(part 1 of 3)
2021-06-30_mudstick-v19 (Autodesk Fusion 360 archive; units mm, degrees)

design "Mudstick" references "Mudstick Plate", "2298K420_METRIC QUICK-GRIP SCREW-CLAMP BUSHING", "N17 48mm"
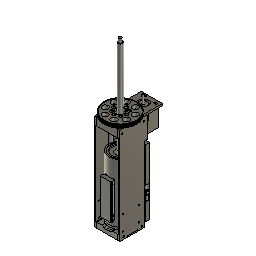
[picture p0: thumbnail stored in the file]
parameter "flexure_w" = 1.5
parameter "gap_w" = 1
parameter "t_sheet_main" = 6.6
parameter "tube_wallthick" = 3.3
parameter "tube_id" = 50.8 (= "( 25.4 * 2 ) * 1 mm")
parameter "tube_len" = 149.225 (= "( 6 * 25.4 ) * 1 mm - ( 0.125 * 25.4 ) * 1 mm")
parameter "id_bspushbearing" = 40
parameter "od_bspushbearing" = 52
parameter "t_bspushbearing" = 7
parameter "hw_m4insert_d" = 5.8
parameter "hw_m4insert_l" = 4.6
parameter "p_teeth" = 2
parameter "pd_pinion" = 10.1859 (= "p_teeth * nt_pinion / PI")
parameter "pd_driven" = 81.4873 (= "p_teeth * nt_driven / PI")
parameter "belt_length" = 280
parameter "c_dist_manuel" = 56.6
parameter "d101" = 7 (= "t_bspushbearing")
parameter "d118" = 2.15 (= "( 4.3 / 2 ) * 1 mm")
sketch "Sketch1" plane through (0, 0, 0) normal (0, 1, 0) x axis (1, 0, 0)
  line L1 (70, 0) -> (0, 0)
  line L2 (70, -115) -> (70, 0)
  line L3 (0, -115) -> (70, -115)
  line L4 (0, 0) -> (0, -115)
  line L5 (35, 0) -> (35, -115)
  point P1 (0, 0)
  point P2 (0, 0)
  point P6 (35, -115)
  point P7 (35, 0)
  point P4 (70, -115)
  point P5 (0, -115)
  horizontal L1
  vertical L2
  horizontal L3
  coincident P1 P2
  vertical L4
  midpoint L3 P6
  midpoint L1 P7
  dimension "d1" distance P4 P5 = 70
  dimension "d2" distance P2 P5 = 115
extrude "Extrude3" new body sketch "Sketch1" profile of L1 L3 L4 L5 against normal blind 10 bodies "Home Plate"
mirror "Mirror3" mirrorStitchTolerance 0
combine "Combine2"
work_plane "WorkPlane1"
sketch "Revolve" plane through (35, -3.3, 55) normal (-1, 0, 0) x axis (0, 1, 0)
  line L1 (-11.3, 46.5347) -> (-8, 46.5347)
  line L2 (-11.3, -102.6903) -> (-11.3, 46.5347)
  line L3 (-36.7, 46.5347) -> (-11.3, 46.5347)
  line L4 (-36.7, -445) -> (-36.7, 155)
  line L5 (-8, -102.6903) -> (-8, 46.5347)
  line L6 (-11.3, -102.6903) -> (-8, -102.6903)
  line L7 (-11.35, 46.5847) -> (-8, 46.5847)
  line L8 (-11.35, 40.5847) -> (-11.35, 46.5847)
  line L9 (-13.35, 40.5847) -> (-11.35, 40.5847)
  line L10 (-34.7, 52.9112) -> (-13.35, 40.5847)
  line L11 (-34.7, 67) -> (-34.7, 52.9112)
  line L12 (-8, 46.5847) -> (-8, 51.5847)
  line L13 (-8, 51.5847) -> (-34.7, 67)
  line L14 (-36.7, -42.863) -> (-11.8, -54.4741)
  line L15 (-7.7, -159.2448) -> (-10.7, -159.2448)
  line L16 (-10.7, -164.2448) -> (-10.7, -159.2448)
  line L17 (-13.7, -167.2448) -> (-10.7, -164.2448)
  line L18 (-13.7, -171.2448) -> (-13.7, -167.2448)
  line L19 (-10.7, -174.2448) -> (-13.7, -171.2448)
  line L20 (-10.7, -179.2448) -> (-10.7, -174.2448)
  line L21 (-7.7, -179.2448) -> (-10.7, -179.2448)
  line L22 (-7.7, -159.2448) -> (-7.7, -179.2448)
  line L23 (-16.7, -177.9448) -> (-15.4, -179.2448)
  line L24 (-16.7, -163.2448) -> (-16.7, -177.9448)
  line L25 (-25.45, -163.2448) -> (-16.7, -163.2448)
  line L26 (-25.45, -189.7448) -> (-25.45, -163.2448)
  line L27 (-16.7, -160.5448) -> (-16.7, -162.7448)
  line L28 (-15.4, -159.2448) -> (-16.7, -160.5448)
  line L29 (-14.7, -159.2448) -> (-15.4, -159.2448)
  line L30 (-14.7, -156.2448) -> (-14.7, -159.2448)
  line L31 (-25.45, -156.2448) -> (-14.7, -156.2448)
  line L32 (-25.45, -162.7448) -> (-25.45, -156.2448)
  line L33 (-16.7, -162.7448) -> (-25.45, -162.7448)
  line L34 (-14.7, -179.2448) -> (-15.4, -179.2448)
  line L35 (-14.7, -180.7448) -> (-14.7, -179.2448)
  line L36 (4.0437, -189.7448) -> (-25.45, -189.7448)
  line L37 (4.0437, -180.7448) -> (-14.7, -180.7448)
  line L38 (4.0437, -189.7448) -> (4.0437, -180.7448)
  line L39 (-16.7, -166.2448) -> (-12.7, -166.2448)
  line L40 (14.807, -180.7448) -> (14.807, -189.7448)
  line L41 (19.9, -180.7448) -> (14.807, -180.7448)
  line L42 (19.9, -189.7448) -> (19.9, -180.7448)
  line L43 (14.807, -189.7448) -> (19.9, -189.7448)
  line L44 (41.05, -127.2448) -> (-1.25, -127.2448)
  line L45 (41.05, -175.2448) -> (41.05, -127.2448)
  line L46 (-1.25, -175.2448) -> (41.05, -175.2448)
  line L47 (-1.25, -127.2448) -> (-1.25, -175.2448)
  line L48 (41.05, -175.2448) -> (-1.25, -127.2448)
  line L49 (-1.25, -175.2448) -> (41.05, -127.2448)
  line L50 (-32.7, -51.2448) -> (-36.7, -51.2448)
  line L51 (-32.7, -66.2448) -> (-32.7, -51.2448)
  line L52 (-31.7, -66.2448) -> (-32.7, -66.2448)
  line L53 (-30.7, -341.2448) -> (-30.7, -104.2448)
  line L54 (-32.7, -341.2448) -> (-30.7, -341.2448)
  line L55 (-32.7, -351.2448) -> (-32.7, -341.2448)
  line L56 (-36.7, -351.2448) -> (-32.7, -351.2448)
  line L57 (-36.7, -53.8968) -> (-19.0837, -62.1114)
  line L58 (-15.5773, -102.1903) -> (-11.8, -102.1903)
  line L59 (-11.8, -58.1903) -> (-11.9581, -58.1903)
  line L60 (-11.8, -54.4741) -> (-11.8, -55.4741)
  line L61 (-12.3, -60.6903) -> (-11.8, -60.1903)
  line L62 (-12.3, -95.9741) -> (-12.3, -60.6903)
  line L63 (-11.9581, -100.1903) -> (-11.8, -100.1903)
  line L64 (-11.8, -96.4741) -> (-11.8, -97.4741)
  line L65 (-12.3, -95.9741) -> (-11.8, -96.4741)
  line L66 (-11.8, -55.4741) -> (-11.9581, -55.4741)
  line L67 (-11.8, -97.4741) -> (-11.9581, -97.4741)
  line L68 (-11.8, -97.4741) -> (-11.8, -58.1903)
  line L69 (-11.8, -102.1903) -> (-11.8, -97.4741)
  line L70 (-16.7, -148.2448) -> (-16.7, -156.2448)
  line L71 (-30.7, -148.2448) -> (-16.7, -148.2448)
  line L72 (-15.5773, -102.1903) -> (-19.0837, -62.1114)
  line L73 (-9, 49.0847) -> (-8, 47.0847)
  line L74 (-8, 51.0847) -> (-9, 49.0847)
  line L75 (-8, 49.0847) -> (-9, 49.0847)
  line L76 (-31.7, -104.2448) -> (-31.7, -66.2448)
  line L77 (-30.7, -104.2448) -> (-31.7, -104.2448)
  line L78 (-25.2, -104.1448) -> (-31.7, -104.1448)
  line L79 (-25.2, -78.1448) -> (-25.2, -104.1448)
  line L80 (-31.7, -78.1448) -> (-25.2, -78.1448)
  line L81 (-31.7, -104.1448) -> (-31.7, -78.1448)
  line L82 (-31.7, -51.1594) -> (-31.7, -56.2283)
  line L83 (-36.7, -48.8279) -> (-31.7, -51.1594)
  line L84 (-25.1, -78.0448) -> (-28.7, -78.0448)
  line L85 (-25.1, -99.1448) -> (-25.1, -78.0448)
  line L86 (-19.3454, -61.9894) -> (-16.0947, -99.1448)
  line L87 (-28.7, -77.0448) -> (-28.7, -78.0448)
  line L88 (-30.7, -74.6613) -> (-28.7, -77.0448)
  line L89 (-30.7, -56.6946) -> (-30.7, -74.6613)
  line L90 (-18.178, -72.4641) -> (-30.7, -66.625)
  line L91 (-15.8414, -99.1719) -> (-11.9581, -98.8322)
  line L92 (-16.0947, -99.1448) -> (-25.1, -99.1448)
  line L93 (4.3937, -189.392) -> (4.3937, -189.7448)
  line L94 (2.8397, -188.4948) -> (4.3937, -189.392)
  line L95 (2.8397, -189.7448) -> (2.8397, -188.4948)
  line L96 (4.3937, -189.7448) -> (4.0437, -189.7448)
  line L97 (-25.45, -185.2448) -> (4.0437, -185.2448)
  line L98 (2.8397, -181.9948) -> (4.3937, -181.0976)
  line L99 (4.3937, -180.7448) -> (4.0437, -180.7448)
  line L100 (4.3937, -181.0976) -> (4.3937, -180.7448)
  line L101 (2.8397, -180.7448) -> (2.8397, -181.9948)
  line L102 (-11.9581, 43.5847) -> (-11.9581, -56.8322)
  line L103 (-11.9581, 42.2266) -> (-11.35, 42.2266)
  line L104 (-11.35, 44.9428) -> (-11.9581, 44.9428)
  line L105 (-11.9581, 43.5847) -> (-11.35, 43.5847)
  circle C1 centre (-11.9581, -56.8322) radius 1.3081
  arc A1 centre (-11.9581, -56.8322) radius 1.3581 clockwise from (-11.9581, -58.1903) to (-11.9581, -55.4741)
  circle C2 centre (-11.9581, -98.8322) radius 1.3081
  arc A2 centre (-11.9581, -98.8322) radius 1.3581 clockwise from (-11.9581, -100.1903) to (-11.9581, -97.4741)
  circle C3 centre (-11.9581, 43.5847) radius 1.3081
  arc A3 centre (-11.9581, 43.5847) radius 1.3581 clockwise from (-11.9581, 42.2266) to (-11.9581, 44.9428)
  point P4 (-11.3, -102.6903)
  point P10 (-11.3, -102.6903)
  point P5 (-36.7, 46.5347)
  point P11 (-8, 46.5847)
  point P18 (-8, 46.5847)
  point P2 (-8, 46.5347)
  point P16 (-34.7, 67)
  point P19 (-34.7, 67)
  point P21 (-36.7, -42.863)
  point P28 (-10.7, -174.2448)
  point P24 (-7.7, -159.2448)
  point P31 (-7.7, -159.2448)
  point P37 (-16.7, -162.7448)
  point P44 (-16.7, -162.7448)
  point P35 (-25.45, -163.2448)
  point P23 (-10.7, -159.2448)
  point P29 (-10.7, -179.2448)
  point P40 (-14.7, -159.2448)
  point P50 (-12.7, -166.2448)
  point P51 (-16.7, -166.2448)
  point P52 (14.807, -189.7448)
  point P56 (14.807, -189.7448)
  point P61 (19.9, -151.2448)
  point P54 (19.9, -180.7448)
  point P49 (4.0437, -189.7448)
  point P48 (4.0437, -180.7448)
  point P62 (-36.7, -51.2448)
  point P68 (-36.7, -351.2448)
  point P71 (-36.7, -53.8968)
  point P73 (-10.65, -56.8322)
  point P72 (-11.9581, -56.8322)
  point P74 (-11.9581, -56.8322)
  point P20 (-11.8, -54.4741)
  point P77 (-11.8, -54.4741)
  point P78 (-11.8, -60.1903)
  point P81 (-11.9581, -98.8322)
  point P82 (-11.8, -100.1903)
  point P84 (-11.9581, -98.8322)
  point P80 (-12.3, -95.9741)
  point P86 (-12.3, -95.9741)
  point P76 (-11.8, -58.1903)
  point P90 (-11.8, -97.4741)
  point P47 (4.0437, -189.7448)
  point P91 (-16.7, -156.2448)
  point P93 (-30.7, -148.2448)
  point P94 (-8, 47.0847)
  point P96 (-8, 51.0847)
  point P97 (-8, 49.0847)
  point P105 (-31.7, -82.2448)
  point P106 (-31.7, -56.2283)
  point P108 (-36.7, -48.8279)
  point P116 (-30.7, -56.6946)
  point P113 (-19.3454, -61.9894)
  point P117 (-30.7, -66.625)
  point P118 (-18.178, -72.4641)
  point P119 (-11.9581, -98.8322)
  point P120 (-15.8414, -99.1719)
  point P121 (-13.311, -98.9505)
  point P125 (2.8397, -189.7448)
  point P126 (4.0437, -185.2448)
  point P127 (-25.45, -185.2448)
  point P130 (4.0437, -180.7448)
  point P122 (4.3937, -189.7448)
  point P131 (4.3937, -180.7448)
  point P123 (4.3937, -189.392)
  point P128 (4.3937, -181.0976)
  point P124 (2.8397, -188.4948)
  point P129 (2.8397, -181.9948)
  point P132 (2.8397, -180.7448)
  point P134 (-11.9581, -56.8322)
  point P133 (-11.9581, 43.5847)
  point P135 (-11.9581, 43.5847)
  point P136 (-11.35, 42.2266)
  point P137 (-11.9581, 42.2266)
  point P138 (-11.9581, 43.5847)
  point P140 (-11.35, 44.9428)
  point P139 (-11.9581, 44.9428)
  point P141 (-11.35, 43.5847)
  point P142 (-11.9581, 43.5847)
  point P8 (3.3, 55)
  point P3 (-11.3, 46.5347)
  point P6 (-36.7, 155)
  point P7 (-36.7, -445)
  point P12 (-11.35, 46.5847)
  point P13 (-11.35, 40.5847)
  point P14 (-13.35, 40.5847)
  point P30 (-7.7, -179.2448)
  point P38 (-16.7, -160.5448)
  point P45 (-14.7, -179.2448)
  point P46 (-14.7, -180.7448)
  point P41 (-14.7, -156.2448)
  point P33 (-16.7, -177.9448)
  point P55 (19.9, -189.7448)
  point P59 (41.05, -175.2448)
  point P60 (-1.25, -175.2448)
  point P58 (41.05, -127.2448)
  point P66 (-32.7, -341.2448)
  point P67 (-32.7, -351.2448)
  point P63 (-32.7, -51.2448)
  point P64 (-32.7, -66.2448)
  point P85 (-11.8, -96.4741)
  point P88 (-11.8, -55.4741)
  point P42 (-25.45, -156.2448)
  point P92 (-16.7, -148.2448)
  point P17 (-8, 51.5847)
  point P95 (-9, 49.0847)
  point P15 (-34.7, 52.9112)
  point P69 (-15.5773, -102.1903)
  point P99 (-31.7, -104.2448)
  point P102 (-25.2, -104.1448)
  point P103 (-25.2, -78.1448)
  point P111 (-25.1, -99.1448)
  point P98 (-31.7, -66.2448)
  point P109 (-28.7, -78.0448)
  point P114 (-28.7, -77.0448)
  point P107 (-31.7, -51.1594)
  point P65 (-30.7, -341.2448)
  point P100 (-30.7, -104.2448)
  horizontal L1
  perpendicular L1 L2
  perpendicular L2 L3
  vertical L4
  perpendicular L3 L5
  perpendicular L5 L6
  coincident P4 P10
  coincident P5 L4
  perpendicular L2 L7
  perpendicular L3 L8
  perpendicular L8 L9
  perpendicular L3 L11
  parallel L11 L12
  coincident P11 P18
  coincident P2 L12
  coincident P16 P19
  coincident L4 P21
  perpendicular L58 L68
  horizontal L15
  perpendicular L15 L16
  perpendicular L15 L18
  perpendicular L17 L19
  perpendicular L18 L21
  vertical L20
  equal L16 L20
  coincident L16 P28
  perpendicular L21 L22
  coincident P24 P31
  vertical L24
  perpendicular L24 L25
  perpendicular L25 L26
  perpendicular L25 L27
  perpendicular L27 L29
  perpendicular L29 L30
  perpendicular L30 L31
  perpendicular L31 L32
  perpendicular L32 L33
  coincident P37 P44
  coincident L24 P44
  coincident P35 L32
  horizontal L34
  perpendicular L34 L35
  coincident P23 L29
  perpendicular L26 L36
  coincident P29 L34
  coincident P40 L35
  perpendicular L35 L37
  perpendicular L37 L38
  coincident L17 P50
  coincident L24 P51
  perpendicular L24 L39
  vertical L40
  perpendicular L40 L41
  perpendicular L41 L42
  perpendicular L42 L43
  coincident P52 P56
  perpendicular L44 L45
  parallel L44 L46
  parallel L45 L47
  horizontal L44
  coincident L48 P61
  coincident L49 P61
  vertical P54 P61
  coincident P49 L43
  coincident P48 L41
  coincident L4 P62
  perpendicular L4 L50
  perpendicular L50 L51
  perpendicular L4 L52
  perpendicular L53 L54
  perpendicular L54 L55
  coincident L4 P68
  perpendicular L4 L56
  coincident L4 P71
  coincident C1 P73
  horizontal P72 P73
  vertical L68
  coincident P72 P74
  horizontal L59
  vertical L60
  coincident P20 P77
  tangent A1 L59
  coincident P78 L68
  vertical L62
  vertical P72 P81
  equal C1 C2
  coincident P82 L68
  perpendicular L63 L68
  coincident P81 P84
  tangent L63 A2
  vertical L64
  coincident P80 P86
  coincident P76 L60
  tangent A1 L66
  horizontal L66
  tangent A2 L67
  coincident L64 P90
  horizontal L67
  collinear L68 L69
  coincident P47 P49
  coincident L31 P91
  perpendicular L31 L70
  coincident L53 P93
  perpendicular L53 L71
  coincident L12 P94
  coincident L12 P96
  midpoint L12 P97
  horizontal L75
  perpendicular L52 L76
  perpendicular L53 L77
  horizontal L78
  vertical L79
  horizontal L80
  vertical L81
  coincident L76 P105
  coincident L57 P106
  vertical L82
  coincident L4 P108
  parallel L57 L83
  perpendicular L76 L84
  perpendicular L84 L85
  parallel L72 L86
  perpendicular L84 L87
  coincident L57 P116
  parallel L87 L89
  coincident L57 P113
  coincident L89 P117
  coincident L72 P118
  parallel L57 L90
  coincident P84 P119
  coincident L72 P120
  perpendicular L72 L91
  coincident A2 P121
  coincident L91 P121
  perpendicular L85 L92
  perpendicular L36 L93
  coincident L36 P125
  perpendicular L36 L95
  horizontal L96
  midpoint L38 P126
  coincident L26 P127
  perpendicular L26 L97
  symmetric P49 L97 P130
  symmetric P122 L97 P131
  symmetric P123 L97 P128
  symmetric P124 L97 P129
  symmetric P125 L97 P132
  equal C1 C3
  coincident P74 P134
  parallel L60 L102
  coincident P133 P135
  coincident L8 P136
  coincident L102 P137
  perpendicular L102 L103
  coincident P133 P138
  coincident L8 P140
  perpendicular L8 L104
  coincident L102 P139
  midpoint L8 P141
  coincident P138 P142
  horizontal L105
  dimension "d75" distance L4 P8 = 40
  dimension "d76" distance P2 P3 = 3.3 (= "tube_wallthick")
  dimension "d80" distance L2 L4 = 25.4 (= "tube_id / 2")
  dimension "d81" distance P3 P4 = 149.225 (= "tube_len")
  dimension "d83" distance P6 P8 = 100
  dimension "d84" distance P7 P8 = 500
  dimension "d85" distance L1 L7 = 0.05
  dimension "d86" distance P12 P13 = 6
  dimension "d87" distance L2 L8 = 0.05
  dimension "d88" distance P13 P14 = 2
  dimension "d92" angle L11 L13 = 60
  dimension "d93" distance L4 L11 = 2
  dimension "d96" angle L10 L14 = 5
  dimension "d103" angle L18 L19 = 45
  dimension "d105" distance P28 P29 = 5
  dimension "d106" distance L4 L20 = 26 (= "od_bspushbearing / 2")
  dimension "d112" distance P30 P31 = 20
  dimension "d113" distance L18 P28 = 3
  dimension "d114" distance L25 L33 = 0.5
  dimension "d115" distance L4 L26 = 11.25 (= "( 22 / 2 ) * 1 mm + 0.25 mm")
  dimension "d116" distance L4 L24 = 20 (= "id_bspushbearing / 2")
  dimension "d120" angle L28 L29 = 45
  dimension "d121" distance P38 L29 = 1.3
  dimension "d122" distance L27 L30 = 2
  dimension "d125" distance P45 P46 = 1.5
  dimension "d127" distance P40 P41 = 3
  dimension "d129" angle L23 L24 = 45
  dimension "d130" distance P33 L34 = 1.3 (= "d121")
  dimension "d146" distance L4 L38 = 40.7437 (= "( pd_driven / 2 mm ) * 1 mm")
  dimension "d149" distance P48 P49 = 9
  dimension "d150" distance P23 L39 = 7 (= "t_bspushbearing")
  dimension "d151" distance P55 P56 = 5.093 (= "pd_pinion / 2")
  dimension "d152" distance L4 L42 = 56.6 (= "c_dist_manuel")
  dimension "d153" distance P59 P60 = 42.3
  dimension "d154" distance P58 P59 = 48
  dimension "d155" distance P30 L46 = 4
  dimension "d158" distance P66 P67 = 10
  dimension "d159" distance P67 P68 = 4 (= "( 8 / 2 ) * 1 mm")
  dimension "d160" distance L4 L53 = 6 (= "( 12 / 2 ) * 1 mm")
  dimension "d161" distance P62 P63 = 4 (= "( 8 / 2 ) * 1 mm")
  dimension "d162" distance P63 P64 = 15
  dimension "d165" distance P62 P68 = 300
  dimension "d173" distance L14 L57 = 10
  dimension "d214" diameter C1 = 2.6162
  dimension "d216" distance L2 P73 = 0.65
  dimension "d217" distance C1 A1 = 0.05
  dimension "d220" distance L2 L68 = 0.5
  dimension "d221" angle L61 L68 = 45
  dimension "d222" distance P76 P78 = 2
  dimension "d223" distance L2 L62 = 1
  dimension "d225" distance L58 P82 = 2
  dimension "d226" distance C2 A2 = 0.05
  dimension "d228" angle L64 L65 = 45
  dimension "d229" distance P85 P90 = 1
  dimension "d230" distance P77 P88 = 1
  dimension "d234" distance L4 P49 = 40.7437
  dimension "d235" distance P42 L36 = 33.5
  dimension "d240" distance P23 L25 = 4
  dimension "d246" distance L4 P41 = 22
  dimension "d247" distance L4 L70 = 20 (= "( 40 / 2 ) * 1 mm")
  dimension "d248" distance P91 P92 = 8
  dimension "d266" distance P8 P19 = 12
  dimension "d280" distance P4 L58 = 0.5
  dimension "d281" distance P17 P18 = 5
  dimension "d282" distance P18 P94 = 0.5
  dimension "d283" distance P95 P97 = 1
  dimension "d284" distance P17 P96 = 0.5
  dimension "d285" distance P15 L14 = 87.6461
  dimension "d286" angle L10 L11 = 60
  dimension "d288" distance P62 P69 = 50.9454
  dimension "d289" distance L4 L76 = 5 (= "( 10 / 2 ) * 1 mm")
  dimension "d290" distance L50 P99 = 53
  dimension "d291" distance L4 L79 = 11.5 (= "( 23 / 2 ) * 1 mm")
  dimension "d292" distance P102 P103 = 26
  dimension "d293" distance L4 L81 = 5 (= "( 10 / 2 ) * 1 mm")
  dimension "d294" distance L52 P105 = 16
  dimension "d298" distance P63 L82 = 1
  dimension "d301" distance P99 L78 = 0.1
  dimension "d302" angle L58 L72 = 95
  dimension "d303" distance P69 L86 = 0.25
  dimension "d305" distance L79 P111 = 0.1
  dimension "d306" distance P103 L84 = 0.1
  dimension "d307" distance P103 L87 = 3.5
  dimension "d308" distance P98 L89 = 1
  dimension "d309" angle L87 L88 = 40
  dimension "d310" distance P109 P114 = 1
  dimension "d311" distance P116 L90 = 9
  dimension "d312" distance P120 P121 = 2.54
  dimension "d315" distance P19 L21 = 246.2448
  dimension "d317" distance P72 P84 = 42
  dimension "d318" distance P63 L83 = 0.5
  dimension "d319" distance L14 P107 = 5.406
  dimension "d320" distance L36 P65 = 151.5
  dimension "d321" distance L71 P100 = 44
  dimension "d322" distance P102 L92 = 5
  dimension "d356" distance P47 L95 = 1.204 (= "0.75 mm + 0.254 mm + 0.2 mm")
  dimension "d357" distance P49 P122 = 0.35
  dimension "d358" distance P124 P125 = 1.25
  dimension "d359" angle L94 L95 = 60
  dimension "d453" distance L4 L22 = 29
  dimension "d551" distance C3 A3 = 0.05
revolve "Revolve1" sketch "Revolve" AlongAngle 360 bodies "Nozzle", "Canister", "Drive Housing", "Drive", "Drive Cap", "Ball Screw"
fillet "Fillet22" radius 12
revolve "Revolve2" sketch "Revolve" AlongAngle 30 (= "( 360 / 12 ) * 1 deg") AgainstAngle 30 (= "( 360 / 12 ) * 1 deg")
chamfer "Chamfer3" distance 8 distance 5
revolve "Revolve3" sketch "Revolve" AlongAngle 360
circular_pattern "C-Pattern1" TotalAngle 360
combine "Combine3"
combine "Combine4"
combine "Combine6"
component_insert "Component Insert1"
joint "Assemble1" alignAngle 0 alignOffsetX 0 alignOffsetY 0 alignOffsetZ 0
sketch "Drive Tooth" plane through (0, 0, 244.7448) normal (0, 0, 1) x axis (-1, 0, 0)
  line L1 (-75.7437, 40) -> (-35, 40)
  line L2 (-75.7314, 39.0001) -> (-35, 40)
  line L3 (-71.7147, 55.2077) -> (-35, 40)
  circle C1 centre (-35, 40) radius 40.7437
  circle C2 centre (-35, 40) radius 11.25
  circle C3 centre (-35, 40) radius 40.7437
  circle C4 centre (-35, 40) radius 40.4897
  circle C5 centre (-35, 40) radius 39.7397
  arc A1 centre (-75.2897, 40) radius 0.55 clockwise from (-74.7397, 40) to (-75.0377, 39.5111)
  arc A2 centre (-75.4958, 40.4) radius 1 clockwise from (-75.0377, 39.5111) to (-75.3542, 39.4101)
  arc A3 centre (-75.3329, 39.2616) radius 0.15 clockwise from (-75.4829, 39.2589) to (-75.3542, 39.4101)
  circle C6 centre (-62.1342, 51.2393) radius 7.3698
  point P3 (-35, 40)
  point P4 (-35, 40)
  point P5 (-75.7437, 40)
  point P6 (-35, 40)
  point P7 (-75.7314, 39.0001)
  point P10 (-74.7397, 40)
  point P15 (-75.4829, 39.2589)
  point P14 (-75.3542, 39.4101)
  point P16 (-75.3542, 39.4101)
  point P9 (-35, 40)
  point P20 (-35, 40)
  point P21 (-71.7147, 55.2077)
  point P18 (-62.1342, 51.2393)
  point P22 (-68.943, 54.0597)
  point P23 (-55.3253, 48.419)
  point P13 (-75.4958, 40.4)
  point P8 (-35, 40)
  concentric C1 C3
  coincident P3 P4
  coincident C1 P5
  horizontal L1
  coincident P3 P6
  coincident C1 P7
  concentric C3 C4
  concentric C3 C5
  tangent C5 A1
  coincident L1 P10
  coincident C5 P10
  tangent A1 A2
  tangent A2 A3
  coincident C4 P15
  coincident P14 P16
  tangent C4 A3
  coincident P9 P20
  coincident C5 P21
  coincident P18 L3
  coincident C6 P22
  coincident L3 P22
  coincident C6 P23
  coincident L3 P23
  dimension "d337" diameter C3 = 81.4873 (= "pd_driven")
  dimension "d338" angle L1 L2 = 1.406 (= "( 180 / nt_driven ) * 1 deg")
  dimension "d342" distance C4 C5 = 0.75
  dimension "d345" distance C3 C4 = 0.254
  dimension "d346" radius A1 = 0.55
  dimension "d347" radius A2 = 1
  dimension "d348" distance L1 P13 = 0.4
  dimension "d349" radius A3 = 0.15
  dimension "d413" angle L1 L3 = 22.5 (= "( 180 / 8 ) * 1 deg")
  dimension "d414" distance P21 P22 = 3
  dimension "d415" distance P8 P23 = 22
extrude "Extrude6" new body sketch "Drive Tooth" profile of C1 L1 L2 C4 A1 A2 A3 to an object
mirror "Mirror4" mirrorStitchTolerance 0.1
circular_pattern "C-Pattern4" TotalAngle 360
combine "Combine7"
revolve "Revolve6" sketch "Revolve" AlongAngle 360
extrude "Extrude7" cut sketch "Drive Tooth" profile of L1 L2 C6 to an object
circular_pattern "C-Pattern5" TotalAngle 360
sketch "Lead Nut Mount" plane through (0, 0, 211.2448) normal (0, 0, -1) x axis (1, 0, 0)
  line L1 (35, 24) -> (35, 40)
  line L2 (30.9585, 24) -> (32.9793, 27.5)
  line L3 (32.9793, 20.5) -> (30.9585, 24)
  line L4 (37.0207, 20.5) -> (32.9793, 20.5)
  line L5 (39.0415, 24) -> (37.0207, 20.5)
  line L6 (37.0207, 27.5) -> (39.0415, 24)
  line L7 (32.9793, 27.5) -> (37.0207, 27.5)
  circle C1 centre (35, 40) radius 11.25
  circle C2 centre (35, 40) radius 22
  circle C3 centre (35, 24) radius 2.125
  point P2 (35, 40)
  point P3 (35, 40)
  point P4 (35, 24)
  point P5 (35, 24)
  point P12 (35, 24)
  point P8 (32.9793, 20.5)
  coincident P2 P3
  vertical L1
  coincident P4 P5
  coincident P4 P12
  horizontal L7
  dimension "d402" distance P3 P4 = 16
  dimension "d403" diameter C3 = 4.25
  dimension "d404" distance P8 L7 = 7
extrude "Extrude11" cut sketch "Lead Nut Mount" profile of C3 to an object
extrude "Extrude12" cut sketch "Lead Nut Mount" profile of C3 L2 L3 L4 L5 L6 L7 to an object from offset -26 (= "-34 mm + 8 mm")
chamfer "Chamfer7" distance 0.5
circular_pattern "C-Pattern6" TotalAngle 360
sketch "Motor Setup" plane through (0, 0, 234.2448) normal (0, 0, 1) x axis (-1, 0, 0)
  line L1 (-14.167, 5.7407) -> (-57.3407, 4.233)
  line L2 (-12.6593, -37.433) -> (-14.167, 5.7407)
  line L3 (-55.833, -38.9407) -> (-12.6593, -37.433)
  line L4 (-57.3407, 4.233) -> (-55.833, -38.9407)
  line L5 (-12.6593, -37.433) -> (-57.3407, 4.233)
  line L6 (-20.0504, -0.5685) -> (-51.0315, -1.6504)
  line L7 (-18.9685, -31.5496) -> (-20.0504, -0.5685)
  line L8 (-49.9496, -32.6315) -> (-18.9685, -31.5496)
  line L9 (-51.0315, -1.6504) -> (-49.9496, -32.6315)
  line L10 (-20.0504, -0.5685) -> (-49.9496, -32.6315)
  line L11 (-35, 4.55) -> (-35, -37.75)
  line L12 (-51.0315, -1.6504) -> (-37.7646, -19.1)
  line L13 (-55.2142, -32.3669) -> (-51.0315, -1.6504)
  line L14 (-20.315, -5.8331) -> (-51.0315, -1.6504)
  line L15 (-62, -40.4407) -> (-62, 73)
  line L16 (-8, -40.4407) -> (-62, -40.4407)
  line L17 (-8, 73) -> (-8, -40.4407)
  line L18 (-13.7022, 6.7575) -> (-12.054, -40.4407)
  line L19 (-58.375, 5.1975) -> (-13.7022, 6.7575)
  line L20 (-60, -6.3652) -> (-58.375, 5.1975)
  line L21 (-62, -6.3652) -> (-60, -6.3652)
  line L22 (-8, 73) -> (-62, 73)
  line L23 (-35, 73) -> (-35, 40)
  circle C1 centre (-35, 40) radius 29
  circle C2 centre (-35, 40) radius 26
  circle C3 centre (-51.0315, -1.6504) radius 1.625
  arc A1 centre (-51.0315, -1.6504) radius 32.9703 clockwise from (-26.9185, -24.1361) to (-31.0768, -27.8963)
  arc A2 centre (-37.7646, -19.1) radius 11.05 clockwise from (-31.0768, -27.8963) to (-44.4524, -10.3037)
  arc A3 centre (-51.0315, -1.6504) radius 10.8703 clockwise from (-43.0815, -9.0639) to (-44.4524, -10.3037)
  arc A4 centre (-35, -16.6) radius 11.05 clockwise from (-43.0815, -9.0639) to (-26.9185, -24.1361)
  arc A5 centre (-51.0315, -1.6504) radius 21.9203 clockwise from (-35, -16.6) to (-37.7646, -19.1)
  arc A6 centre (-51.0315, -1.6504) radius 32.625 clockwise from (-18.4264, -0.5118) to (-18.7048, -6.0523)
  arc A7 centre (-20.315, -5.8331) radius 1.625 clockwise from (-18.7048, -6.0523) to (-21.9251, -5.6138)
  arc A8 centre (-51.0315, -1.6504) radius 29.375 clockwise from (-21.6744, -0.6252) to (-21.9251, -5.6138)
  arc A9 centre (-20.0504, -0.5685) radius 1.625 clockwise from (-21.6744, -0.6252) to (-18.4264, -0.5118)
  arc A10 centre (-51.0315, -1.6504) radius 31 clockwise from (-20.0504, -0.5685) to (-20.315, -5.8331)
  arc A11 centre (-51.0315, -1.6504) radius 45.4656 clockwise from (-17.7801, -32.6579) to (-23.5142, -37.8432)
  arc A12 centre (-24.4977, -36.5496) radius 1.625 clockwise from (-23.5142, -37.8432) to (-25.4812, -35.256)
  arc A13 centre (-51.0315, -1.6504) radius 42.2156 clockwise from (-20.1569, -30.4414) to (-25.4812, -35.256)
  arc A14 centre (-18.9685, -31.5496) radius 1.625 clockwise from (-20.1569, -30.4414) to (-17.7801, -32.6579)
  arc A15 centre (-51.0315, -1.6504) radius 43.8406 clockwise from (-18.9685, -31.5496) to (-24.4977, -36.5496)
  arc A16 centre (-51.0315, -1.6504) radius 32.625 clockwise from (-49.8929, -34.2555) to (-55.4335, -33.9771)
  arc A17 centre (-55.2142, -32.3669) radius 1.625 clockwise from (-55.4335, -33.9771) to (-54.995, -30.7568)
  arc A18 centre (-51.0315, -1.6504) radius 29.375 clockwise from (-50.0063, -31.0075) to (-54.995, -30.7568)
  arc A19 centre (-49.9496, -32.6315) radius 1.625 clockwise from (-50.0063, -31.0075) to (-49.8929, -34.2555)
  arc A20 centre (-51.0315, -1.6504) radius 31 clockwise from (-49.9496, -32.6315) to (-55.2142, -32.3669)
  point P7 (-35, -16.6)
  point P8 (-51.0315, -1.6504)
  point P14 (-51.0315, -1.6504)
  point P21 (-51.0315, -1.6504)
  point P19 (-35, -16.6)
  point P20 (-37.7646, -19.1)
  point P22 (-37.7646, -19.1)
  point P23 (-51.0315, -1.6504)
  point P30 (-51.0315, -1.6504)
  point P9 (-20.0504, -0.5685)
  point P28 (-20.0504, -0.5685)
  point P37 (-51.0315, -1.6504)
  point P10 (-18.9685, -31.5496)
  point P35 (-18.9685, -31.5496)
  point P44 (-51.0315, -1.6504)
  point P11 (-49.9496, -32.6315)
  point P42 (-49.9496, -32.6315)
  point P36 (-24.4977, -36.5496)
  point P45 (-51.0315, -1.6504)
  point P43 (-55.2142, -32.3669)
  point P46 (-55.2142, -32.3669)
  point P29 (-20.315, -5.8331)
  point P47 (-20.315, -5.8331)
  point P53 (-12.054, -40.4407)
  point P57 (-62, -6.3652)
  point P2 (-35, 40)
  point P58 (-35, 40)
  point P59 (-35, 73)
  point P60 (-35, 69)
  point P3 (-57.3407, 4.233)
  point P6 (-55.833, -38.9407)
  point P51 (-8, 73)
  point P4 (-14.167, 5.7407)
  point P55 (-58.375, 5.1975)
  point P56 (-60, -6.3652)
  perpendicular L1 L2
  parallel L1 L3
  parallel L2 L4
  equal L1 L4
  midpoint P7 L5
  perpendicular L6 L7
  parallel L6 L8
  parallel L7 L9
  parallel L1 L6
  coincident L5 P8
  midpoint P7 L10
  coincident P8 P14
  tangent A1 A2
  tangent A2 A3
  tangent A3 A4
  tangent A1 A4
  coincident P14 P21
  coincident P7 P19
  coincident P20 P22
  coincident P21 P23
  tangent A6 A7
  tangent A7 A8
  tangent A8 A9
  tangent A6 A9
  coincident P21 P30
  coincident P9 P28
  tangent A11 A12
  tangent A12 A13
  tangent A13 A14
  tangent A11 A14
  coincident P14 P37
  coincident P10 P35
  tangent A16 A17
  tangent A17 A18
  tangent A18 A19
  tangent A16 A19
  coincident P14 P44
  coincident P11 P42
  equal C3 A19
  equal C3 A9
  equal C3 A14
  coincident L12 P36
  coincident P37 P45
  coincident P43 P46
  coincident P29 P47
  vertical L15
  perpendicular L15 L16
  perpendicular L16 L17
  perpendicular L18 L19
  parallel L2 L18
  coincident L16 P53
  coincident L15 P57
  perpendicular L15 L21
  perpendicular L17 L22
  coincident P2 P58
  midpoint L22 P59
  vertical L23
  coincident C1 P60
  coincident L23 P60
  dimension "d361" distance P3 P6 = 43.2
  dimension "d362" distance P8 P11 = 31
  dimension "d370" angle L6 L11 = 92
  dimension "d371" diameter C3 = 3.25
  dimension "d372" radius A4 = 11.05 (= "( 22.1 / 2 ) * 1 mm")
  dimension "d373" distance P19 P20 = 2.5
  dimension "d374" = 9.8
  dimension "d375" angle L12 L13 = 45
  dimension "d376" angle L12 L14 = 45
  dimension "d378" distance L15 P51 = 54
  dimension "d379" distance P6 L16 = 1.5
  dimension "d382" distance P4 L18 = 0.5
  dimension "d384" distance P4 L19 = 1
  dimension "d385" angle L19 L20 = 100 (= "90 deg + 10 deg")
  dimension "d386" distance L4 P55 = 1
  dimension "d387" distance P56 P57 = 2
  dimension "d393" distance P59 P60 = 4
extrude "Extrude17" cut sketch "Motor Setup" profile of C1 L15 L17 to an object
extrude "Extrude9" add sketch "Motor Setup" profile of C1 L15 L16 L17 L18 L19 L20 L21 L22 to an object
extrude "Extrude10" add sketch "Motor Setup" profile of C3 A1 A2 A3 A4 A6 A7 A8 A9 A11 A12 A13 A14 A16 A17 A18 A19 L16 L18 L19 L20 against normal blind 5
fillet "Fillet27" radius 0.5
fillet "Fillet28" radius 3
fillet "Fillet29" radius 1
component_insert "Component Insert2"
joint "Assemble2" alignAngle 90 alignOffsetX 0 alignOffsetY 0 alignOffsetZ 0
sketch "Nozzle Cup Revolve" plane through (35, -5, 57.5) normal (-1, 0, 0) x axis (0, 1, 0)
  line L1 (-6.3, 54.0847) -> (-33, 69.5)
  line L2 (-27.8038, 68.5) -> (-27.8038, 66.5)
  line L3 (-5.8, 68.5) -> (-27.8038, 68.5)
  line L4 (-5.8, 55.0847) -> (-5.8, 68.5)
  line L5 (-8.0321, 55.0847) -> (-5.8, 55.0847)
  line L6 (-35, -442.5) -> (-35, 157.5)
  point P4 (-27.8038, 66.5)
  point P8 (-8.0321, 55.0847)
  point P3 (-6.3, 54.0847)
  point P2 (-33, 69.5)
  point P5 (-27.8038, 68.5)
  coincident L1 P4
  vertical L2
  perpendicular L2 L3
  perpendicular L3 L4
  coincident L1 P8
  perpendicular L4 L5
  dimension "d420" distance P3 L4 = 0.5
  dimension "d421" distance P3 L5 = 1
  dimension "d422" distance P2 L3 = 1
  dimension "d423" distance P4 P5 = 2
revolve "Revolve7" sketch "Nozzle Cup Revolve" AlongAngle 360 bodies "Lower Cup"
sketch "Nozzle Cup Square Out" plane through (0, 0, -11) normal (0, 0, -1) x axis (1, 0, 0)
  line L1 (8, 73) -> (8, -40.4407)
  line L2 (62, 73) -> (8, 73)
  line L3 (62, 10.5) -> (62, 73)
  line L4 (8, 10.5) -> (62, 10.5)
  line L5 (35, 73) -> (35, 40)
  line L6 (70, 10) -> (0, 10)
  circle C1 centre (35, 40) radius 7.1962
  circle C2 centre (35, 40) radius 29.2
  point P4 (8, 73)
  point P5 (8, 73)
  point P8 (8, 10.5)
  point P9 (35, 40)
  point P10 (35, 40)
  point P11 (35, 73)
  coincident P4 P5
  perpendicular L1 L2
  perpendicular L2 L3
  coincident L1 P8
  perpendicular L1 L4
  coincident P9 P10
  midpoint L2 P11
  vertical L5
  dimension "d440" distance L4 L6 = 0.5
extrude "Extrude18" cut sketch "Nozzle Cup Square Out" profile of C2 L1 L3 to an object
extrude "Extrude14" add sketch "Nozzle Cup Square Out" profile of C2 L1 L2 L3 L4 to an object
sketch "Wing" plane through (8, 0, 0) normal (-1, 0, 0) x axis (0, -1, 0)
  line L1 (73, 214.2448) -> (-40.4407, 214.2448)
  line L2 (-40.4407, 234.2448) -> (73, 234.2448)
  line L3 (73, -11) -> (73, 214.2448)
  line L4 (73, -11) -> (10.5, -11)
  line L5 (10.5, 214.2448) -> (10.5, 2.4153)
  line L6 (20.5415, -5) -> (18.5207, -8.5)
  line L7 (18.5207, -1.5) -> (20.5415, -5)
  line L8 (14.4793, -1.5) -> (18.5207, -1.5)
  line L9 (12.4585, -5) -> (14.4793, -1.5)
  line L10 (14.4793, -8.5) -> (12.4585, -5)
  line L11 (18.5207, -8.5) -> (14.4793, -8.5)
  line L12 (9.9793, 227.7448) -> (14.0207, 227.7448)
  line L13 (16.0415, 224.2448) -> (14.0207, 220.7448)
  line L14 (14.0207, 220.7448) -> (9.9793, 220.7448)
  line L15 (9.9793, 220.7448) -> (7.9585, 224.2448)
  line L16 (7.9585, 224.2448) -> (9.9793, 227.7448)
  line L17 (14.0207, 227.7448) -> (16.0415, 224.2448)
  line L18 (17, 226.2448) -> (17, 222.2448)
  line L19 (40, 500) -> (40, -100)
  line L20 (63, 226.2448) -> (63, 222.2448)
  line L21 (17, 224.2448) -> (12, 224.2448)
  line L22 (65.9793, 220.7448) -> (70.0207, 220.7448)
  line L23 (65.9793, 227.7448) -> (63.9585, 224.2448)
  line L24 (72.0415, 224.2448) -> (70.0207, 227.7448)
  line L25 (70.0207, 220.7448) -> (72.0415, 224.2448)
  line L26 (70.0207, 227.7448) -> (65.9793, 227.7448)
  line L27 (63.9585, 224.2448) -> (65.9793, 220.7448)
  line L28 (27.5, 231.2448) -> (27.5, 234.2448)
  line L29 (52.5, 231.2448) -> (27.5, 231.2448)
  line L30 (52.5, 234.2448) -> (52.5, 231.2448)
  line L31 (4, 179.2448) -> (4, 234.2448)
  line L32 (10.5, 179.2448) -> (4, 179.2448)
  line L33 (-40.4407, 214.2448) -> (-40.4407, 234.2448)
  line L34 (61.4793, -8.5) -> (65.5207, -8.5)
  line L35 (65.5207, -1.5) -> (61.4793, -1.5)
  line L36 (59.4585, -5) -> (61.4793, -8.5)
  line L37 (61.4793, -1.5) -> (59.4585, -5)
  line L38 (67.5415, -5) -> (65.5207, -1.5)
  line L39 (65.5207, -8.5) -> (67.5415, -5)
  line L40 (27.5, -8) -> (27.5, -11)
  line L41 (52.5, -8) -> (27.5, -8)
  line L42 (52.5, -11) -> (52.5, -8)
  line L43 (73, 234.2448) -> (73, 214.2448)
  line L44 (20, 16) -> (10.1, 16)
  line L45 (20, 4) -> (20, 16)
  line L46 (10.1, 4) -> (20, 4)
  line L47 (10.1, 16) -> (10.1, 4)
  line L48 (10.5, 2.4153) -> (10.5, -11)
  circle C1 centre (16.5, -5) radius 2.125
  circle C2 centre (12, 224.2448) radius 2.125
  circle C3 centre (68, 224.2448) radius 2.125
  circle C4 centre (63.5, -5) radius 2.125
  point P4 (73, 214.2448)
  point P6 (73, 214.2448)
  point P7 (73, -11)
  point P9 (73, -11)
  point P11 (10.5, 214.2448)
  point P12 (16.5, -5)
  point P19 (16.5, -5)
  point P20 (12, 224.2448)
  point P23 (12, 224.2448)
  point P28 (17, 222.2448)
  point P32 (63, 222.2448)
  point P29 (17, 226.2448)
  point P33 (63, 226.2448)
  point P34 (12, 224.2448)
  point P35 (17, 224.2448)
  point P21 (9.9793, 227.7448)
  point P41 (70.0207, 227.7448)
  point P22 (9.9793, 220.7448)
  point P37 (70.0207, 220.7448)
  point P36 (68, 224.2448)
  point P24 (14.0207, 227.7448)
  point P39 (65.9793, 227.7448)
  point P25 (16.0415, 224.2448)
  point P44 (63.9585, 224.2448)
  point P26 (7.9585, 224.2448)
  point P42 (72.0415, 224.2448)
  point P27 (14.0207, 220.7448)
  point P38 (65.9793, 220.7448)
  point P40 (68, 224.2448)
  point P45 (27.5, 234.2448)
  point P48 (52.5, 234.2448)
  point P49 (40, 231.2448)
  point P50 (4, 234.2448)
  point P52 (10.5, 179.2448)
  point P13 (18.5207, -8.5)
  point P60 (61.4793, -8.5)
  point P14 (20.5415, -5)
  point P54 (59.4585, -5)
  point P15 (18.5207, -1.5)
  point P56 (61.4793, -1.5)
  point P16 (14.4793, -1.5)
  point P59 (65.5207, -1.5)
  point P17 (12.4585, -5)
  point P58 (67.5415, -5)
  point P18 (14.4793, -8.5)
  point P55 (65.5207, -8.5)
  point P53 (63.5, -5)
  point P61 (27.5, -11)
  point P64 (52.5, -11)
  point P65 (40, -8)
  point P71 (20, 10)
  point P10 (10.5, 2.4153)
  point P73 (10.5, 2.4153)
  point P8 (10.5, -11)
  point P72 (10.5, -11)
  point P46 (27.5, 231.2448)
  point P47 (52.5, 231.2448)
  point P51 (4, 179.2448)
  point P70 (10, 0)
  point P67 (20, 16)
  point P68 (20, 4)
  point P1 (0, 0)
  coincident P4 P6
  perpendicular L1 L3
  coincident P7 P9
  perpendicular L4 L5
  coincident L1 P11
  coincident P12 P19
  horizontal L11
  coincident P20 P23
  horizontal L14
  symmetric P28 L19 P32
  symmetric P29 L19 P33
  coincident P23 P34
  midpoint L18 P35
  horizontal L21
  symmetric P21 L19 P41
  symmetric P22 L19 P37
  symmetric P23 L19 P36
  symmetric P24 L19 P39
  symmetric P25 L19 P44
  symmetric P26 L19 P42
  symmetric P27 L19 P38
  symmetric C2 L19 C3
  symmetric L19 P34 P40
  coincident L2 P45
  perpendicular L2 L28
  perpendicular L28 L29
  coincident L2 P48
  perpendicular L2 L30
  midpoint L29 P49
  coincident L19 P49
  coincident L2 P50
  perpendicular L1 L31
  coincident L5 P52
  perpendicular L5 L32
  symmetric C1 L19 C4
  symmetric P13 L19 P60
  symmetric P14 L19 P54
  symmetric P15 L19 P56
  symmetric P16 L19 P59
  symmetric P17 L19 P58
  symmetric P18 L19 P55
  symmetric P19 L19 P53
  coincident L4 P61
  perpendicular L4 L40
  perpendicular L40 L41
  coincident L4 P64
  perpendicular L4 L42
  coincident L41 P65
  midpoint L41 P65
  coincident L19 P65
  equal L29 L41
  equal L30 L42
  horizontal L44
  vertical L45
  horizontal L46
  vertical L47
  midpoint L45 P71
  coincident P10 P73
  coincident P8 P72
  horizontal L4
  dimension "d427" diameter C1 = 4.25
  dimension "d428" distance P16 L11 = 7
  dimension "d429" distance L4 P19 = 6
  dimension "d431" diameter C2 = 4.25
  dimension "d432" distance P21 L14 = 7
  dimension "d433" distance P34 P35 = 5
  dimension "d434" distance P45 P46 = 3
  dimension "d435" distance P46 P47 = 25
  dimension "d436" distance P50 P51 = 55
  dimension "d437" distance P23 L31 = 8
  dimension "d462" distance L47 P70 = 0.1
  dimension "d463" distance P67 P68 = 12
  dimension "d464" distance P1 P67 = 20
  dimension "d465" distance P1 P71 = 10
  dimension "d486" distance P19 L48 = 6
extrude "Extrude13" cut sketch "Wing" profile of C1 C2 C3 C4 to an object
sketch "Pull Out Relief" plane through (0, -73, 0) normal (0, -1, 0) x axis (1, 0, 0)
  line L1 (8, 2.4153) -> (62, 2.4153)
  line L2 (8, -11) -> (8, 2.4153)
  line L3 (62, -11) -> (8, -11)
  line L4 (62, 2.4153) -> (62, -11)
  line L5 (29, -2) -> (21.3526, 2.4153)
  line L6 (41, -2) -> (29, -2)
  line L7 (48.6474, 2.4153) -> (41, -2)
  line L8 (35, -2) -> (35, 2.4153)
  point P6 (21.3526, 2.4153)
  point P9 (48.6474, 2.4153)
  point P10 (35, 2.4153)
  point P11 (35, -2)
  point P7 (29, -2)
  point P8 (41, -2)
  point P12 (8, -5)
  coincident L1 P6
  parallel L1 L6
  coincident L1 P9
  midpoint L1 P10
  midpoint L6 P11
  vertical L8
  dimension "d445" distance P7 P8 = 12
  dimension "d446" angle L5 L6 = 30
  dimension "d447" angle L6 L7 = 30 (= "d446")
  dimension "d450" distance L6 P12 = 3
extrude "Extrude15" cut sketch "Pull Out Relief" profile of L1 L5 L6 L7 to an object
fillet "Fillet31" radius 12
extrude "Extrude16" new body sketch "Wing" profile of L1 L2 L3 L4 L5 C1 L6 L7 L8 L9 L10 L11 L12 L13 L14 L15 L16 L17 C2 L22 L23 C3 L24 L25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 blind 5 from offset 0.1 bodies "West Wing"
offset_faces "OffsetFaces3" distance -0.15
extrude "Extrude21" add sketch "Wing" profile of L2 L4 L28 L29 L30 L40 L41 L42 to an object
mirror "Mirror6" mirrorStitchTolerance 0.1 bodies "Drive Housing (1)"
combine "Combine9"
combine "Combine10" bodies "Drive Housing (1)"
extrude "Extrude22" of existing geometry to an object
offset_faces "OffsetFaces4" distance -0.5
sketch "Sketch14" plane through (0, 0, 214.2448) normal (0, 0, -1) x axis (1, 0, 0)
  line L1 (7.9, 50.8734) -> (7.9, 29.1266)
  line L2 (5.8, 73) -> (5.8, 40)
  line L3 (7.9, 73) -> (5.8, 73)
  line L4 (7.9, 73) -> (7.9, 50.8734)
  arc A1 centre (35, 40) radius 29.2 clockwise from (7.9, 29.1266) to (7.9, 50.8734)
  point P5 (5.8, 40)
  point P3 (7.9, 50.8734)
  point P8 (7.9, 50.8734)
  point P7 (7.9, 73)
  point P9 (7.9, 73)
  point P10 (8, 73)
  midpoint A1 P5
  tangent A1 L2
  vertical L2
  coincident P3 P8
  parallel L1 L4
  coincident P7 P9
  horizontal L3
  coincident L3 P10
extrude "Extrude23" cut sketch "Sketch14" to an object
sketch "Sketch15" plane through (0, 0, 2.4153) normal (0, 0, 1) x axis (-1, 0, 0)
  curve K1 (-21.3526, 66.4738) -> (-18.9283, 61.6557)
  curve K2 (-51.0717, 61.6557) -> (-48.6474, 66.4738)
  line L1 (-48.6474, 73) -> (-48.6474, 66.4738)
  line L2 (-62, 73) -> (-48.6474, 73)
  line L3 (-62, 10.5) -> (-62, 73)
  line L4 (-8, 10.5) -> (-62, 10.5)
  line L5 (-8, 73) -> (-8, 10.5)
  line L6 (-21.3526, 73) -> (-8, 73)
  line L7 (-21.3526, 66.4738) -> (-21.3526, 73)
  line L8 (-35, 10.5) -> (-35, 40)
  line L9 (-13, 16) -> (-13, 10.5)
  line L10 (-17, 16) -> (-9, 16)
  line L11 (-26.3843, 10.1) -> (-26.3843, 12.1)
  line L12 (-35, 10.1) -> (-35, 10.5)
  line L13 (-2.9, 10.1) -> (-35, 10.1)
  line L14 (-2.9, 10.5) -> (-2.9, 10.1)
  line L15 (-8, 10.5) -> (-2.9, 10.5)
  line L16 (-7.9, 10.5) -> (-7.9, 29.1266)
  arc A1 centre (-35, 40) radius 26.9679 clockwise from (-18.9283, 61.6557) to (-51.0717, 61.6557)
  arc A2 centre (-35, 40) radius 29.2 clockwise from (-5.8, 40) to (-7.9, 29.1266)
  arc A3 centre (-35, 40) radius 29.2 clockwise from (-7.9, 29.1266) to (-35, 10.8)
  point P13 (-7.9, 29.1266)
  point P18 (-7.9, 29.1266)
  point P15 (-35, 40)
  point P16 (-35, 40)
  point P19 (-35, 40)
  point P20 (-35, 10.5)
  point P17 (-35, 10.8)
  point P21 (-13, 10.5)
  point P22 (-13, 16)
  point P25 (-26.3843, 12.1)
  point P10 (-8, 10.5)
  point P30 (-8, 10.5)
  point P29 (-2.9, 10.5)
  point P31 (-2.9, 10.5)
  point P26 (-26.3843, 10.1)
  point P33 (-7.9, 29.1266)
  point P34 (-7.9, 10.5)
  point P23 (-9, 16)
  point P24 (-17, 16)
  point P32 (0, 10)
  coincident P13 P18
  coincident P15 P16
  coincident P15 P19
  midpoint L4 P20
  coincident P17 L8
  coincident L4 P21
  perpendicular L4 L9
  horizontal L10
  midpoint P22 L10
  coincident A3 P25
  perpendicular L4 L11
  perpendicular L4 L12
  perpendicular L12 L13
  perpendicular L13 L14
  perpendicular L12 L15
  coincident P10 P30
  coincident P29 P31
  coincident P26 L13
  coincident P13 P33
  coincident L15 P34
  perpendicular L15 L16
  dimension "d487" distance P23 P24 = 8
  dimension "d488" distance L8 L9 = 22
  dimension "d489" distance P21 P22 = 5.5
  dimension "d490" distance P25 P26 = 2
  dimension "d494" distance L13 P32 = 0.1
extrude "Extrude24" new body sketch "Sketch15" profile of L4 L5 A3 L11 L13 L14 L15 L16 to an object offset -0.25 from offset 0.25
sketch "Plate Mount" plane through (0, -10.1, 0) normal (0, 1, 0) x axis (-1, 0, 0)
  line L1 (-26.3843, 114.75) -> (-2.9, 114.75)
  line L2 (-26.3843, 2.6653) -> (-26.3843, 114.75)
  line L3 (-2.9, 2.6653) -> (-26.3843, 2.6653)
  line L4 (-2.9, 114.75) -> (-2.9, 2.6653)
  line L5 (-57, 12.4153) -> (-13, 12.4153)
  line L6 (-57, 102.4153) -> (-57, 12.4153)
  line L7 (-13, 102.4153) -> (-57, 102.4153)
  line L8 (-13, 12.4153) -> (-13, 102.4153)
  line L9 (-35, 12.4153) -> (-35, 2.4153)
  line L10 (-57, 159.4153) -> (-57, 102.4153)
  circle C1 centre (-13, 12.4153) radius 2.125
  circle C2 centre (-13, 102.4153) radius 2.125
  circle C3 centre (-13, 102.4153) radius 4.25
  circle C4 centre (-13, 12.4153) radius 4.25
  circle C5 centre (-57, 159.4153) radius 2.125
  circle C6 centre (-57, 159.4153) radius 4.25
  point P10 (-35, 2.4153)
  point P11 (-35, 2.4153)
  point P12 (-35, 12.4153)
  point P6 (-13, 12.4153)
  point P13 (-13, 12.4153)
  point P9 (-13, 102.4153)
  point P14 (-13, 102.4153)
  point P17 (-57, 159.4153)
  point P18 (-57, 159.4153)
  point P8 (-57, 102.4153)
  point P7 (-57, 12.4153)
  horizontal L5
  vertical L6
  horizontal L7
  vertical L8
  coincident P10 P11
  midpoint L5 P12
  vertical L9
  coincident P6 P13
  coincident P9 P14
  concentric C2 C3
  concentric C1 C4
  equal C3 C4
  equal C1 C2
  perpendicular L7 L10
  concentric C5 C6
  coincident P17 P18
  dimension "d495" distance P8 P9 = 44
  dimension "d496" distance P7 P8 = 90
  dimension "d497" distance P11 P12 = 10
  dimension "d498" diameter C2 = 4.25
  dimension "d499" diameter C3 = 8.5
  dimension "d522" diameter C5 = 4.25
  dimension "d523" diameter C6 = 8.5
  dimension "d524" distance P8 P17 = 57
extrude "Extrude25" cut sketch "Plate Mount" profile of C1 C2 to an object
extrude "Extrude26" sketch "Plate Mount" profile of C1 C2 C3 C4 to an object
chamfer "Chamfer9" distance 2.125 (= "( ( 8.5 - 4.25 ) / 2 ) * 1 mm")
combine "Combine11"
component_insert "Component Insert4"
joint "Assemble3" alignAngle 0 alignOffsetX 0 alignOffsetY 0 alignOffsetZ 0
mirror "Mirror5" mirrorStitchTolerance 0.1 bodies "East Wing"
sketch "Sketch17" plane through (2.9, 0, 0) normal (-1, 0, 0) x axis (0, -1, 0)
  line L1 (10.5, 114.75) -> (10.5, 179.2448)
  line L2 (10.1, 114.75) -> (10.5, 114.75)
  line L3 (10.1, 2.6653) -> (10.1, 114.75)
  line L4 (10.5, 2.6653) -> (10.1, 2.6653)
  line L5 (10.5, -11) -> (10.5, 2.6653)
  line L6 (27.35, -11) -> (10.5, -11)
  line L7 (27.35, -7.85) -> (27.35, -11)
  line L8 (52.65, -7.85) -> (27.35, -7.85)
  line L9 (52.65, -11) -> (52.65, -7.85)
  line L10 (73, -11) -> (52.65, -11)
  line L11 (73, 234.2448) -> (73, -11)
  line L12 (52.65, 234.2448) -> (73, 234.2448)
  line L13 (52.65, 231.0948) -> (52.65, 234.2448)
  line L14 (27.35, 231.0948) -> (52.65, 231.0948)
  line L15 (27.35, 234.2448) -> (27.35, 231.0948)
  line L16 (4, 234.2448) -> (27.35, 234.2448)
  line L17 (4, 179.2448) -> (4, 234.2448)
  line L18 (10.5, 179.2448) -> (4, 179.2448)
  line L19 (30.1, 161.9153) -> (10.5, 161.9153)
  line L20 (30.1, 114.9153) -> (30.1, 161.9153)
  line L21 (10.5, 114.9153) -> (30.1, 114.9153)
  line L22 (25.1, 121.9153) -> (25.1, 154.9153)
  line L23 (30.1, 138.4153) -> (25.1, 138.4153)
  circle C1 centre (12, 224.2448) radius 2.125
  circle C2 centre (16.5, -5) radius 2.125
  circle C3 centre (63.5, -5) radius 2.125
  circle C4 centre (68, 224.2448) radius 2.125
  point P24 (10.5, 161.9153)
  point P27 (10.5, 114.9153)
  point P30 (25.1, 138.4153)
  point P31 (30.1, 138.4153)
  point P28 (25.1, 154.9153)
  coincident L1 P24
  perpendicular L1 L19
  perpendicular L19 L20
  coincident L1 P27
  perpendicular L1 L21
  midpoint L22 P30
  midpoint L20 P31
  horizontal L23
  dimension "d514" distance L20 P28 = 5
  dimension "d515" distance L19 P28 = 7
extrude "Extrude27" cut sketch "Sketch17" profile of L1 L19 L20 L21 to an object
fillet "Fillet32" radius 3
extrude "Extrude28" add of existing geometry to an object offset -1
extrude "Extrude29" cut sketch "Plate Mount" profile of C5 to an object
extrude "Extrude30" cut sketch "Plate Mount" profile of C5 C6 to an object from offset -5
chamfer "Chamfer10" distance 2.125 (= "( ( 8.5 - 4.25 ) / 2 ) * 1 mm")
sketch "Handle" plane through (0, 0, 157.6903) normal (0, 0, 1) x axis (-1, 0, 0)
  line L1 (-20, 75.6748) -> (-23.876, 66.4565)
  line L2 (-35, 68.7) -> (-35, 40)
  line L3 (-35, 78.7) -> (-35, 68.7)
  line L4 (-24.7035, 72.2284) -> (-23.4884, 67.3783)
  line L5 (-24.7035, 72.2284) -> (-21.938, 71.0656)
  line L6 (-24.7035, 72.2284) -> (-20.3876, 74.753)
  line L7 (-35, 75.6748) -> (-20, 75.6748)
  line L8 (-21.1547, 77.6748) -> (-20, 75.6748)
  line L9 (-35, 77.6748) -> (-21.1547, 77.6748)
  circle C1 centre (-35, 40) radius 28.7
  circle C2 centre (-35, 40) radius 25.4
  arc A1 centre (-35, 40) radius 38.7 clockwise from (-35, 78.7) to (-20, 75.6748)
  point P3 (-23.876, 66.4565)
  point P2 (-35, 40)
  point P5 (-35, 40)
  point P6 (-35, 68.7)
  point P7 (-35, 40)
  point P8 (-35, 78.7)
  point P9 (-23.4884, 67.3783)
  point P11 (-21.938, 71.0656)
  point P12 (-20.3876, 74.753)
  point P10 (-24.7035, 72.2284)
  point P13 (-24.7035, 72.2284)
  point P14 (-35, 75.6748)
  point P16 (-35, 77.6748)
  point P4 (-20, 75.6748)
  coincident C1 P3
  coincident P2 L1
  coincident P2 P5
  coincident C1 P6
  vertical L2
  parallel L2 L3
  coincident P5 P7
  coincident L3 P8
  coincident L1 P9
  midpoint L1 P11
  perpendicular L1 L5
  symmetric P9 L5 P12
  symmetric P10 L5 P13
  coincident L3 P14
  perpendicular L3 L7
  perpendicular L3 L9
  coincident L3 P16
  dimension "d531" distance C1 A1 = 10
  dimension "d532" distance P4 L2 = 15
  dimension "d535" distance P10 P11 = 3
  dimension "d536" distance P3 P9 = 1
  dimension "d545" angle L7 L8 = 60
  dimension "d546" distance P14 L9 = 2
extrude "Extrude31" sketch "Handle" profile of C1 L1 L3 A1 L4 L6 L7 L8 L9 blind 90 from offset 15 bodies "Handle"
extrude "Extrude32" sketch "Handle" profile of L1 L4 L6 to an object offset -10 from offset 10
fillet "Fillet33" radius 2
fillet "Fillet34" radius 2
mirror "Mirror7" mirrorStitchTolerance 0.1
